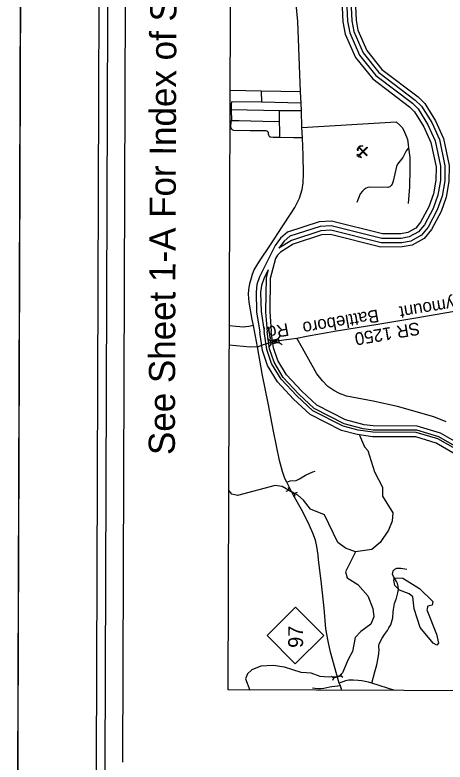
# Model space of a CAD drawing. Extents: x 2364794 to 2387902, y 795230 to 810426.
# Drawn here: x 2364794 to 2365657, y 800262 to 801761 of the extents above; entities that cross this region are included whole.
import ezdxf

# ---------------------------------------------------------------- set-up
doc = ezdxf.new("R2010")
doc.units = 0
for name, color, linetype in [('Default', 7, 'Continuous'), ('Mis Object Lines', 7, 'Continuous'), ('Old_Level_21', 7, 'Continuous'), ('Old_Level_22', 7, 'Continuous'), ('Plan Sheet CELL', 7, 'Continuous'), ('Plot Label CELL', 7, 'Continuous'), ('User Information Notes CELL', 7, 'Continuous')]:
    doc.layers.add(name, color=color, linetype=linetype)

msp = doc.modelspace()

# ---------------------------------------------------------------- linework, layer by layer
at = {"layer": 'Default'}
for p, q in [((2365227.7, 801571), (2365227.8, 801549.6)), ((2365322, 801111.2), (2365326.2, 801117.5)), ((2365299.5, 801112), (2365305.8, 801107.9)), ((2365323.5, 801103.8), (2365329.8, 801099.6)), ((2365303.2, 801094), (2365307.4, 801100.3)), ((2365338, 800805.6), (2365343.3, 800807.3)), ((2365342, 800812.7), (2365343.3, 800807.3)), ((2365343.3, 800807.3), (2365354.8, 800800.7)), ((2365360.1, 800802.4), (2365354.8, 800800.7)), ((2365356.1, 800795.4), (2365354.8, 800800.7)), ((2365299.5, 800515.9), (2365356.6, 800572.6)), ((2365356.6, 800572.6), (2365413.3, 800515.5)), ((2365356.2, 800458.9), (2365299.5, 800515.9)), ((2365413.3, 800515.5), (2365356.2, 800458.9)), ((2365429.1, 800433.9), (2365433.8, 800431)), ((2365431.2, 800426.1), (2365433.8, 800431)), ((2365433.8, 800431), (2365446.6, 800434.4)), ((2365449.2, 800439.3), (2365446.6, 800434.4)), ((2365451.3, 800431.5), (2365446.6, 800434.4))]:
    msp.add_line(p, q, dxfattribs=at)
for points in [[(2365221.1, 800406.3), (2365228.7, 802558.1), (2367168.3, 802551.2), (2367160.7, 800399.4)], [(2365221.1, 800406.3), (2365228.7, 802558.1), (2367168.3, 802551.2), (2367160.7, 800399.4)], [(2365481.5, 801488.6), (2365481.3, 801489.4), (2365481.1, 801490.1), (2365481.1, 801491.1), (2365481.2, 801492), (2365481.6, 801493.3), (2365482.3, 801494.9), (2365483.2, 801496.2), (2365484.1, 801497.1), (2365485.2, 801497.8), (2365486.6, 801498.4), (2365487.6, 801498.7), (2365488.9, 801498.8), (2365490.2, 801498.8), (2365491.4, 801498.6), (2365489.7, 801498.3), (2365488.7, 801498), (2365487.9, 801497.7), (2365486.6, 801497), (2365485.5, 801496.2), (2365484.8, 801495.7), (2365483.7, 801494.4), (2365482.9, 801493.3), (2365482.3, 801492), (2365481.8, 801490.7), (2365481.6, 801489.4)], [(2365484.3, 801478.9), (2365483.4, 801479.8), (2365499.9, 801496.1), (2365500.7, 801495.2)], [(2365499.8, 801478.9), (2365500.6, 801479.7), (2365484.3, 801496.1), (2365483.5, 801495.3)], [(2365481.8, 801482.2), (2365479.7, 801480.2), (2365483.1, 801477.1), (2365488.8, 801475.4)], [(2365305.8, 801107.9), (2365322, 801111.2), (2365323.6, 801103.6), (2365307.4, 801100.3)], [(2365321.6, 801103.5), (2365308.3, 801104.4), (2365320.2, 801110.3), (2365314.8, 801105.7)]]:
    msp.add_lwpolyline(points, close=True, dxfattribs=at)
msp.add_lwpolyline([(2365280.3, 801095.2), (2365292.1, 801099.6), (2365306.3, 801103.8), (2365315.5, 801105.9)], dxfattribs=at)
at = {"layer": 'Mis Object Lines'}
for points in [[(2365009.5, 810236.7), (2364972.8, 799876.6)], [(2365044.4, 810201.5), (2365009.3, 800261.6)]]:
    msp.add_lwpolyline(points, dxfattribs=at)
at = {"layer": 'Old_Level_21'}
msp.add_lwpolyline([(2364835.2, 810426.2), (2364793.5, 798638.3), (2372493.4, 798611.1), (2372535.1, 810399)], close=True, dxfattribs=at)
at = {"layer": 'Old_Level_22'}
msp.add_lwpolyline([(2372336.7, 798702.6), (2372377.9, 810368.1), (2364992.2, 810394.2), (2364951, 798728.7)], close=True, dxfattribs=at)
at = {"layer": 'Plan Sheet CELL'}
msp.add_line((2364793.5, 798638.3), (2364835.2, 810426.2), dxfattribs=at)
at = {"layer": 'Plot Label CELL'}
for p, q in [((2365287.4, 801608.1), (2365226, 801609.9)), ((2365287.4, 801608.1), (2365288, 801586.6)), ((2365366.9, 801607.1), (2365287.4, 801608.1)), ((2365367.9, 801584.6), (2365288, 801586.6)), ((2365324.5, 801569.1), (2365227.7, 801571)), ((2365324.5, 801548.5), (2365324.5, 801569.1)), ((2365368.5, 801569), (2365324.5, 801569.1)), ((2365280.3, 801095.2), (2365272, 801138.2))]:
    msp.add_line(p, q, dxfattribs=at)
for points in [[(2365272, 801138.2), (2365269.4, 801149.8), (2365263.9, 801185), (2365262.5, 801201.1), (2365263.1, 801209.8), (2365265.2, 801222.2), (2365268.1, 801233.6), (2365270.5, 801241.3), (2365273.8, 801249.4), (2365284.3, 801266.9), (2365306.1, 801299.9), (2365329.9, 801336.2), (2365347.7, 801363.4), (2365355.2, 801374.7), (2365364.4, 801393.4), (2365369.9, 801410.9), (2365371.8, 801424.2), (2365372.7, 801441.5), (2365371.8, 801479.8), (2365370.3, 801515), (2365369.5, 801535.6), (2365368.5, 801569), (2365367.9, 801584.6), (2365366.9, 801607.1), (2365361.3, 801748), (2365357, 801789.9)], [(2365288, 801586.6), (2365229.1, 801586.9), (2365227.8, 801586.1), (2365227.4, 801583.1), (2365227.2, 801577.3), (2365227.7, 801571)], [(2365325.4, 801515.4), (2365311.7, 801515.6), (2365306.8, 801515.8), (2365305, 801516.2), (2365304.2, 801517.4), (2365303.1, 801519.8), (2365302.4, 801522.1), (2365302.1, 801525.3), (2365301, 801527), (2365299.3, 801528.1), (2365297.2, 801528.6), (2365290.5, 801528.5), (2365265.9, 801528.6), (2365232.8, 801529.4), (2365230.8, 801529.9), (2365228.5, 801531.9), (2365227.4, 801534), (2365226.9, 801536.3), (2365226.8, 801539.6), (2365227.8, 801549.6)], [(2365227.8, 801549.6), (2365243.6, 801549.5), (2365314.4, 801547.7), (2365324.5, 801548.5)], [(2365325.4, 801515.4), (2365325.3, 801528), (2365324.5, 801548.5)], [(2365369.5, 801535.6), (2365558.4, 801546.6), (2365566.8, 801539.7), (2365570.6, 801535.2), (2365573.4, 801530.6), (2365579, 801516.9), (2365581.1, 801511.2), (2365582.7, 801501.6), (2365583.2, 801494.8)], [(2365370.3, 801515), (2365352.4, 801514.9), (2365325.4, 801515.4)], [(2365583.2, 801494.8), (2365578.4, 801488.7), (2365571.8, 801475.5), (2365561.2, 801461.6), (2365559.1, 801457.2), (2365552.6, 801427.4), (2365550.4, 801421.9), (2365548.3, 801418.8), (2365546.1, 801416.6), (2365542, 801415.1), (2365507.2, 801415.4), (2365501.5, 801414.9), (2365498.1, 801413.7), (2365494.6, 801411.3), (2365490.7, 801407.8), (2365486.4, 801402.1), (2365484, 801396.8), (2365481.9, 801390.4), (2365479.3, 801385.2)], [(2365583.2, 801494.8), (2365586, 801475), (2365586.2, 801451.6), (2365585, 801416.6), (2365582.5, 801382.9)], [(2365315.5, 801105.9), (2365323.2, 801107.6), (2365359, 801112.6), (2365378.3, 801116.4), (2365439, 801127), (2365522, 801140.4), (2365598, 801153.6), (2365695, 801169.9), (2365750.6, 801176.4), (2365791.6, 801181.1), (2365883.3, 801194.2)], [(2365272, 801138.2), (2365263, 801136.2), (2365256.7, 801135), (2365252.1, 801134.4), (2365237.4, 801135.9), (2365223.7, 801137.1)], [(2365659.2, 800944.6), (2365634.4, 800954.9), (2365561, 800975.7), (2365512.6, 800986.4), (2365458.9, 800996), (2365445.1, 801001.6), (2365433.4, 801007.2), (2365421.6, 801015.4), (2365410.8, 801026.9), (2365399.5, 801041.2), (2365370.9, 801092.3), (2365359, 801112.6)], [(2365280.3, 801095.2), (2365265.5, 801094.5), (2365223.5, 801098.4)], [(2365444.1, 800420.1), (2365426.5, 800482.4), (2365421.8, 800504), (2365417.6, 800528.9), (2365413.8, 800570.6), (2365408.8, 800619.3), (2365402.9, 800668), (2365402.2, 800676.8), (2365399.2, 800694.4), (2365396.4, 800706.9), (2365391.3, 800721.3), (2365384.6, 800736.5), (2365371, 800764), (2365351.9, 800798.1), (2365339.3, 800823.4), (2365335.3, 800831), (2365332.8, 800837.1), (2365330.3, 800844.7), (2365324.5, 800867), (2365312.6, 800926.1), (2365301.8, 800982.2), (2365290.6, 801037.9), (2365280.3, 801095.2)], [(2365339.3, 800823.4), (2365345.8, 800826.1), (2365357.6, 800826.6), (2365364.8, 800829.9), (2365376.8, 800837.2), (2365391.1, 800844.1), (2365395.9, 800845.7)], [(2365509.8, 800420), (2365515.9, 800442.7), (2365519.5, 800457), (2365522.4, 800470.5), (2365523.8, 800479.5), (2365524.2, 800487.6), (2365523.7, 800492), (2365523.9, 800495.3), (2365524.6, 800498.3), (2365526.3, 800502.7), (2365530.4, 800510.6), (2365535.1, 800517.9), (2365541.2, 800525.8), (2365543.7, 800530.8), (2365547.8, 800537.4), (2365552.1, 800551), (2365552.4, 800563.3), (2365553.1, 800567.9), (2365555.4, 800579.7), (2365559.4, 800590.9), (2365562.2, 800601.4), (2365563, 800608.4), (2365562.7, 800613.8), (2365561.1, 800620), (2365558.9, 800624.3), (2365553.2, 800633.9), (2365551.1, 800638.7), (2365552.8, 800645.2), (2365555.9, 800648.6), (2365560, 800650.6), (2365567.9, 800650.6), (2365579.7, 800649)], [(2365446.6, 800414.6), (2365429.7, 800412.9), (2365425.4, 800412.2), (2365413.4, 800409.3), (2365408.2, 800408.8), (2365400.9, 800408.7), (2365390.9, 800409.8)], [(2365556.2, 800405.1), (2365509.8, 800420), (2365502.8, 800422.3), (2365489.9, 800424.7), (2365482.1, 800425.4), (2365472.6, 800425.9), (2365463.9, 800425.9), (2365456.7, 800424.8), (2365444.1, 800420.1)], [(2365449.4, 800405.5), (2365446.6, 800414.6), (2365444.1, 800420.1)]]:
    msp.add_lwpolyline(points, dxfattribs=at)
at = {"layer": 'User Information Notes CELL'}
for points in [[(2365353.5, 802095), (2365444.8, 801893.8), (2365451.6, 801747.6), (2365456.5, 801722.9), (2365476.7, 801676.1), (2365511.5, 801632.9), (2365585.2, 801577), (2365595.5, 801566.9), (2365614.2, 801536.7), (2365628, 801505.5), (2365638.5, 801456.7), (2365638, 801429.8), (2365633.5, 801402.1), (2365624, 801376)], [(2365360.7, 802101.9), (2365361, 802100.8), (2365454, 801896), (2365460.9, 801748.7), (2365465.5, 801725.6), (2365484.8, 801681), (2365518, 801639.6), (2365591.2, 801584), (2365602.8, 801572.7), (2365622.4, 801541.1), (2365636.9, 801508.4), (2365647.8, 801457.6), (2365647.3, 801428.9), (2365642.5, 801399.8), (2365632.7, 801372.8)], [(2365369.2, 802103.7), (2365462.5, 801898.1), (2365469.5, 801749.8), (2365473.8, 801728.2), (2365492.2, 801685.5), (2365524.1, 801645.8), (2365596.9, 801590.6), (2365609.6, 801578.2), (2365630.1, 801545.2), (2365645.2, 801511.1), (2365656.5, 801458.4), (2365655.9, 801428.1), (2365650.9, 801397.6), (2365640.9, 801369.9)], [(2365379, 802102.6), (2365470.9, 801900.1), (2365478, 801750.8), (2365481.9, 801730.8), (2365499.6, 801689.9), (2365530.1, 801652), (2365602.5, 801597), (2365616.3, 801583.5), (2365637.6, 801549.1), (2365653.3, 801513.7), (2365665, 801459.3), (2365664.4, 801427.3), (2365659.2, 801395.4), (2365648.9, 801367)], [(2365624, 801376), (2365607.6, 801345.4), (2365597.7, 801333.1), (2365581.7, 801324.6), (2365568, 801321.9), (2365530.8, 801321.7), (2365429, 801347.4), (2365404, 801345.9), (2365340.7, 801325.2), (2365326.7, 801313.6), (2365315.7, 801298.6), (2365284.6, 801235.4), (2365279.1, 801220.3), (2365277.3, 801204.6), (2365278.6, 801165.2), (2365284.9, 801124.4)], [(2365632.7, 801372.8), (2365615.3, 801340.4), (2365603.7, 801325.9), (2365584.8, 801315.8), (2365568.9, 801312.8), (2365529.7, 801312.5), (2365428.2, 801338.1), (2365405.8, 801336.8), (2365345.2, 801317), (2365333.5, 801307.3), (2365323.2, 801293.2)], [(2365648.9, 801367), (2365629.6, 801330.9), (2365614.9, 801312.5), (2365590.6, 801299.5), (2365570.6, 801295.7), (2365527.6, 801295.4), (2365426.5, 801320.9), (2365409, 801319.9), (2365351.9, 801301.1), (2365326.6, 801285.5), (2365320.1, 801279.1), (2365316.7, 801272.6), (2365306, 801232.4), (2365304.9, 801165.9), (2365307.8, 801125.9)], [(2365640.9, 801369.9), (2365622.6, 801335.6), (2365609.4, 801319.1), (2365587.8, 801307.6), (2365569.8, 801304.1), (2365528.6, 801303.8), (2365427.3, 801329.4), (2365407.4, 801328.2), (2365348.3, 801308.8), (2365323.2, 801293.2)], [(2365301.9, 801249.6), (2365293.1, 801231.7), (2365288.1, 801218.2), (2365286.5, 801204.2), (2365287.8, 801166.1), (2365294, 801125.8)], [(2365301.9, 801249.6), (2365297.6, 801233.6), (2365296.5, 801165.7), (2365299.4, 801125.3)], [(2365480.3, 800918.9), (2365448.7, 800927.2), (2365385.9, 800959.2), (2365352.8, 800990), (2365320.4, 801024.9), (2365300.2, 801058), (2365290.3, 801087.9), (2365284.9, 801124.4)], [(2365482.6, 800927.8), (2365452, 800935.8), (2365391.2, 800966.9), (2365359.3, 800996.5), (2365327.7, 801030.5), (2365308.6, 801061.9), (2365299.3, 801090), (2365294, 801125.7)], [(2365492.1, 800930.8), (2365453.9, 800940.8), (2365394.3, 800971.2), (2365363.1, 801000.2), (2365332, 801033.7), (2365313.5, 801064.1), (2365304.4, 801091.2), (2365299.4, 801125.3)], [(2365494.2, 800938.9), (2365456.9, 800948.7), (2365399.1, 800978.2), (2365369, 801006.2), (2365338.7, 801038.8), (2365321.1, 801067.7), (2365312.6, 801093.2), (2365307.8, 801125.9)], [(2365995.8, 800490.8), (2365972.1, 800558.5), (2365961.8, 800583.1), (2365900.3, 800656.3), (2365855.9, 800730.6), (2365750.4, 800834.6), (2365713.3, 800877), (2365689.6, 800897.8), (2365647.4, 800922), (2365600.9, 800936.1), (2365512.6, 800936.3), (2365494.2, 800938.9)], [(2365984.1, 800487.4), (2365960.1, 800554.6), (2365950.9, 800576.4), (2365889.9, 800649), (2365845.9, 800722.8), (2365741.2, 800825.9), (2365704.4, 800868.1), (2365682.2, 800887.4), (2365642.4, 800910.3), (2365599, 800923.5), (2365511.8, 800923.7), (2365482.6, 800927.8)], [(2365987.5, 800488.7), (2365964.1, 800555.9), (2365954.6, 800578.7), (2365893.4, 800651.5), (2365849.2, 800725.4), (2365744.3, 800828.8), (2365707.4, 800871.1), (2365684.7, 800890.9), (2365644.1, 800914.3), (2365599.7, 800927.8), (2365512.1, 800928), (2365492.1, 800930.8)], [(2365485.1, 800917.6), (2365494.8, 800894.3), (2365501.9, 800887.1), (2365515, 800844.4), (2365530.9, 800813.6), (2365531.2, 800795.3), (2365552.2, 800761.8), (2365550.6, 800745.4), (2365543.4, 800727), (2365526.4, 800702.4), (2365510, 800688.5), (2365477.2, 800683.7)], [(2365978.2, 800484.4), (2365951.4, 800551.8), (2365943.1, 800571.6), (2365882.5, 800643.7), (2365838.6, 800717.1), (2365734.6, 800819.6), (2365697.9, 800861.6), (2365676.9, 800880), (2365638.7, 800901.9), (2365597.7, 800914.4), (2365511.1, 800914.6), (2365480.3, 800918.9)], [(2365477.2, 800683.7), (2365457.2, 800690.8), (2365441.7, 800702.6), (2365414.9, 800757.9), (2365386.4, 800769.5), (2365372.9, 800787.5), (2365360.9, 800797.1), (2365349, 800804), (2365338, 800810), (2365329.5, 800814.7), (2365315.5, 800817), (2365240.4, 800796.4), (2365228.5, 800799.1), (2365222.5, 800807.3)], [(2365477.2, 800683.7), (2365456.8, 800643.5), (2365460.5, 800631.6), (2365481.5, 800618.1), (2365501.7, 800595.5), (2365511.9, 800570.1), (2365514, 800552.8), (2365507.8, 800538.2), (2365487.9, 800523.5), (2365476.1, 800511.5), (2365471.1, 800483.3), (2365461.9, 800467.7), (2365450.9, 800440.7), (2365444.7, 800434.6), (2365440.2, 800432.7), (2365422, 800431.9), (2365405.8, 800433.5), (2365388.3, 800439.8), (2365368.2, 800441.4), (2365334.4, 800452.1), (2365311.7, 800455.5), (2365287, 800454.3), (2365268.9, 800446.9), (2365259.9, 800438.7), (2365256.3, 800428.6), (2365264.7, 800406.1)], [(2365643.8, 800500.2), (2365640.3, 800496.5), (2365633, 800500.1), (2365607, 800531.8), (2365594.9, 800569), (2365592.2, 800593.6), (2365584.8, 800599.1), (2365565.5, 800607), (2365556.2, 800616.1), (2365553.6, 800626.9), (2365555.2, 800631.5), (2365571.8, 800630.8), (2365605.6, 800610.1), (2365632, 800583.9), (2365630.5, 800576.6), (2365622.3, 800574.7), (2365620.4, 800567.4), (2365639.8, 800518.4), (2365643.8, 800500.2)]]:
    msp.add_lwpolyline(points, dxfattribs=at)

# ---------------------------------------------------------------- texts
at = {"layer": 'Default'}
for s, height, rotation, p in [('Rockymount', 25.36, 189.1852, (2365749.5, 801206)), ('Battleboro', 25.36, 189.8888, (2365521.5, 801170.5)), ('Rd.', 25.36, 190.6677, (2365340.5, 801143)), ('-', 10.4, 8.7703, (2365487.2, 801120.3)), ('97', 29.9, 89.7976, (2365371.7, 800490.8))]:
    msp.add_text(s, height=height, rotation=rotation, dxfattribs=at).set_placement(p)
at = {"layer": 'Mis Object Lines'}
msp.add_text('See Sheet 1-A For Index of Sheets', height=52.5, rotation=89.7976, dxfattribs=at).set_placement((2365114.4, 800877.9))
at = {"layer": 'Plot Label CELL'}
msp.add_text('SR 1250', height=25.36, rotation=189.6814, dxfattribs=at).set_placement((2365603.8, 801144.9))

doc.saveas('drawing.dxf')
